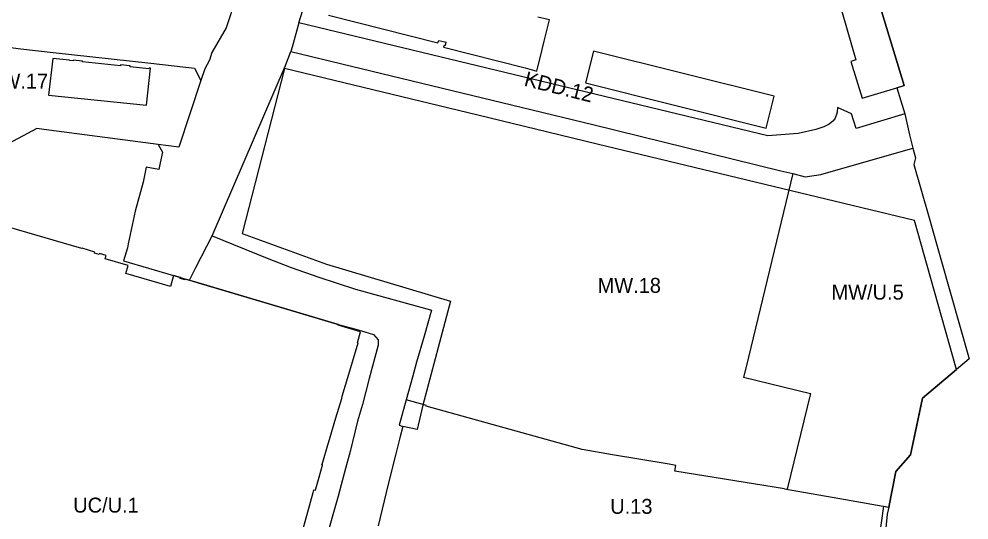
# Model space of a CAD drawing. Extents: x 7424052 to 7425705, y 5546602 to 5547569.
# Drawn here: x 7425164.6 to 7425482.3, y 5546917.7 to 5547085.1 of the extents above; entities that cross this region are included whole.
import ezdxf

# ---------------------------------------------------------------- set-up
doc = ezdxf.new("R2010")
doc.units = 0
for name, color, linetype in [('linie rozgraniczające', 7, 'Continuous'), ('nieprzekraczalne linie zabudowy', 7, 'Continuous'), ('obowiazujace linie zabudowy', 7, 'Continuous'), ('przeznaczenia terenów', 7, 'Continuous')]:
    doc.layers.add(name, color=color, linetype=linetype)

msp = doc.modelspace()

# ---------------------------------------------------------------- linework, layer by layer
at = {"layer": 'linie rozgraniczające'}
for p, q in [((7425258.21, 5547083.79), (7425262.57, 5547097.9)), ((7425237.13, 5547092.01), (7425233.89, 5547082.13)), ((7425233.89, 5547082.13), (7425229.11, 5547073.88)), ((7425258.21, 5547083.79), (7425255.98, 5547075.66)), ((7425305.74, 5547072.33), (7425258.21, 5547083.79)), ((7425160.05, 5547075.79), (7425165.13, 5547075.14)), ((7425165.13, 5547075.14), (7425176.01, 5547073.94)), ((7425255.98, 5547075.66), (7425255.44, 5547074.17)), ((7425176.01, 5547073.94), (7425208.62, 5547070.34)), ((7425228.29, 5547071.34), (7425226.68, 5547068.43)), ((7425229.11, 5547073.88), (7425228.29, 5547071.34)), ((7425253.74, 5547069.49), (7425255.44, 5547074.17)), ((7425255.44, 5547074.17), (7425356.5, 5547049.81)), ((7425415.01, 5547045.99), (7425305.74, 5547072.33)), ((7425208.62, 5547070.34), (7425223.21, 5547068.63)), ((7425223.21, 5547068.63), (7425225.42, 5547064.54)), ((7425226.68, 5547068.43), (7425225.42, 5547064.54)), ((7425229.17, 5547012.59), (7425253.74, 5547069.49)), ((7425225.42, 5547064.54), (7425218.05, 5547042.21)), ((7425438.33, 5547055.56), (7425438.25, 5547053.97)), ((7425442.95, 5547053.38), (7425438.33, 5547055.56)), ((7425438.01, 5547053.15), (7425437.4, 5547051.75)), ((7425438.25, 5547053.97), (7425438.01, 5547053.15)), ((7425444.55, 5547048.46), (7425442.95, 5547053.38)), ((7425460.79, 5547053.42), (7425444.55, 5547048.46)), ((7425460.79, 5547053.42), (7425462.35, 5547046.32)), ((7425356.5, 5547049.81), (7425419.41, 5547034.39)), ((7425433.8, 5547049.07), (7425431.08, 5547048.19)), ((7425435.55, 5547049.93), (7425433.8, 5547049.07)), ((7425436.8, 5547050.91), (7425435.55, 5547049.93)), ((7425437.4, 5547051.75), (7425436.8, 5547050.91)), ((7425170.57, 5547048.5), (7425159.48, 5547042.54)), ((7425172.88, 5547048.19), (7425170.57, 5547048.5)), ((7425211.16, 5547043.12), (7425172.88, 5547048.19)), ((7425425.13, 5547046.83), (7425415.01, 5547045.99)), ((7425431.08, 5547048.19), (7425425.13, 5547046.83)), ((7425211.16, 5547043.12), (7425212.55, 5547040.53)), ((7425218.05, 5547042.21), (7425211.16, 5547043.12)), ((7425212.55, 5547040.53), (7425211.81, 5547036.98)), ((7425432.7, 5547033.14), (7425463.51, 5547041.87)), ((7425463.51, 5547041.87), (7425464.41, 5547038.69)), ((7425211.81, 5547036.98), (7425211.35, 5547034.78)), ((7425464.41, 5547038.69), (7425463.86, 5547036.5)), ((7425207.08, 5547035.52), (7425206.12, 5547030.53)), ((7425211.35, 5547034.78), (7425207.08, 5547035.52)), ((7425423.34, 5547033.41), (7425407.72, 5546968.9)), ((7425419.41, 5547034.39), (7425423.34, 5547033.41)), ((7425423.34, 5547033.41), (7425427.55, 5547032.35)), ((7425427.55, 5547032.35), (7425432.7, 5547033.14)), ((7425206.12, 5547030.53), (7425203.47, 5547020.9)), ((7425203.47, 5547020.9), (7425201.1, 5547010)), ((7425223.75, 5547002.02), (7425229.17, 5547012.59)), ((7425229.17, 5547012.59), (7425247.59, 5547005.15)), ((7425200.82, 5547008.57), (7425199.5, 5547004.32)), ((7425201.1, 5547010), (7425200.82, 5547008.57)), ((7425247.59, 5547005.15), (7425255.54, 5547002.04)), ((7425199.5, 5547004.32), (7425216.28, 5546999.34)), ((7425221.58, 5546997.79), (7425223.75, 5547002.02)), ((7425255.54, 5547002.04), (7425264.86, 5546998.81)), ((7425216.28, 5546999.34), (7425216.28, 5546999.34)), ((7425216.28, 5546999.34), (7425218.6, 5546998.67)), ((7425218.6, 5546998.67), (7425220.21, 5546998.19)), ((7425220.21, 5546998.19), (7425221.58, 5546997.79)), ((7425264.86, 5546998.81), (7425277.12, 5546994.82)), ((7425221.58, 5546997.79), (7425224.49, 5546996.88)), ((7425224.49, 5546996.88), (7425247.74, 5546990)), ((7425277.12, 5546994.82), (7425302.21, 5546987.85)), ((7425247.74, 5546990), (7425270.99, 5546983.13)), ((7425302.56, 5546987.75), (7425300.08, 5546979.12)), ((7425302.21, 5546987.85), (7425302.56, 5546987.75)), ((7425270.99, 5546983.13), (7425271.32, 5546983.01)), ((7425271.32, 5546983.01), (7425277.24, 5546981.48)), ((7425277.24, 5546981.48), (7425280.21, 5546980.49)), ((7425280.21, 5546980.49), (7425283.12, 5546979.63)), ((7425283.12, 5546979.63), (7425284.73, 5546977.89)), ((7425300.08, 5546979.12), (7425297.55, 5546970.38)), ((7425284.65, 5546976.04), (7425281.71, 5546964.96)), ((7425284.73, 5546977.89), (7425284.65, 5546976.04)), ((7425297.55, 5546970.38), (7425296.17, 5546965.43)), ((7425407.72, 5546968.9), (7425406.88, 5546965.41)), ((7425281.71, 5546964.96), (7425279.42, 5546956.23)), ((7425296.17, 5546965.43), (7425294.07, 5546957.83)), ((7425406.88, 5546965.41), (7425429.3, 5546959.97)), ((7425429.3, 5546959.97), (7425421.53, 5546927.92)), ((7425294.07, 5546957.83), (7425291.69, 5546949.4)), ((7425300.82, 5546955.97), (7425294.07, 5546957.83)), ((7425279.42, 5546956.23), (7425277.8, 5546950.71)), ((7425300.77, 5546955.76), (7425300.82, 5546955.97)), ((7425346.85, 5546942.88), (7425300.77, 5546955.76)), ((7425277.8, 5546950.71), (7425275.28, 5546940.53)), ((7425291.69, 5546949.4), (7425292.9, 5546948.93)), ((7425292.9, 5546948.93), (7425291.92, 5546945.18)), ((7425291.92, 5546945.18), (7425290.57, 5546939.81)), ((7425352.87, 5546941.21), (7425346.85, 5546942.88)), ((7425363.04, 5546939.46), (7425352.87, 5546941.21)), ((7425275.28, 5546940.53), (7425273.75, 5546934.91)), ((7425290.57, 5546939.81), (7425288.06, 5546929.59)), ((7425371.82, 5546937.95), (7425363.04, 5546939.46)), ((7425381.99, 5546936.27), (7425371.82, 5546937.95)), ((7425462.73, 5546939.43), (7425457.87, 5546933.9)), ((7425273.75, 5546934.91), (7425271.28, 5546925.67)), ((7425384.28, 5546935.88), (7425381.99, 5546936.27)), ((7425383.93, 5546934.01), (7425384.28, 5546935.88)), ((7425420.55, 5546928.09), (7425383.93, 5546934.01)), ((7425457.87, 5546933.9), (7425455.47, 5546921.95)), ((7425288.06, 5546929.59), (7425284.64, 5546915.69)), ((7425271.28, 5546925.67), (7425264.86, 5546903.09)), ((7425420.55, 5546928.09), (7425440.98, 5546924.47)), ((7425440.98, 5546924.47), (7425455.47, 5546921.95)), ((7425455.47, 5546921.95), (7425454.97, 5546919.66)), ((7425454.97, 5546919.66), (7425454, 5546910.51))]:
    msp.add_line(p, q, dxfattribs=at)
for points in [[(7425444.26, 5547116.94), (7425452.42, 5547089.88), (7425460.58, 5547062.82)], [(7425460.58, 5547062.82), (7425459.36, 5547062.45), (7425458.15, 5547062.09)], [(7425458.15, 5547062.09), (7425459.47, 5547057.75), (7425460.79, 5547053.42)], [(7425462.35, 5547046.32), (7425462.93, 5547044.09), (7425463.51, 5547041.87)], [(7425463.86, 5547036.5), (7425468.71, 5547019.43), (7425473.08, 5547004.04), (7425482.3, 5546971.57), (7425482.3, 5546971.57)], [(7425482.3, 5546971.57), (7425474.54, 5546964.95), (7425466.78, 5546958.33)], [(7425466.78, 5546958.33), (7425464.85, 5546949.31), (7425462.73, 5546939.43)]]:
    msp.add_lwpolyline(points, dxfattribs=at)
at = {"layer": 'nieprzekraczalne linie zabudowy'}
for p, q in [((7425253.31, 5547068.54), (7425239.25, 5547013.36)), ((7425468.27, 5547002.67), (7425464.07, 5547017.79)), ((7425239.25, 5547013.36), (7425267.37, 5547003.21)), ((7425267.37, 5547003.21), (7425308.87, 5546990.81)), ((7425478.12, 5546968), (7425468.27, 5547002.67)), ((7425308.87, 5546990.81), (7425299.66, 5546956)), ((7425466.78, 5546958.33), (7425478.12, 5546968)), ((7425462.73, 5546939.43), (7425466.78, 5546958.33)), ((7425299.66, 5546956), (7425297.72, 5546947.88)), ((7425292.9, 5546948.93), (7425291.92, 5546945.18)), ((7425297.72, 5546947.88), (7425292.9, 5546948.93)), ((7425291.92, 5546945.18), (7425290.57, 5546939.81)), ((7425290.57, 5546939.81), (7425288.06, 5546929.59)), ((7425457.87, 5546933.9), (7425462.73, 5546939.43)), ((7425455.47, 5546921.95), (7425457.87, 5546933.9)), ((7425288.06, 5546929.59), (7425284.64, 5546915.69)), ((7425452.26, 5546911.19), (7425453.8, 5546922.24)), ((7425453.8, 5546922.24), (7425455.47, 5546921.95))]:
    msp.add_line(p, q, dxfattribs=at)
at = {"layer": 'obowiazujace linie zabudowy'}
for p, q in [((7425435.97, 5547100.84), (7425444.5, 5547071.39)), ((7425460.58, 5547062.82), (7425452.42, 5547089.88)), ((7425444.5, 5547071.39), (7425442.82, 5547070.87)), ((7425442.82, 5547070.87), (7425446.53, 5547058.59)), ((7425446.53, 5547058.59), (7425458.15, 5547062.09)), ((7425458.15, 5547062.09), (7425460.58, 5547062.82))]:
    msp.add_line(p, q, dxfattribs=at)
for points in [[(7425268.05, 5547086.33), (7425304.7, 5547077.14), (7425304.93, 5547077.95), (7425307.02, 5547077.45), (7425307.37, 5547077.37), (7425307.09, 5547076.17), (7425306.73, 5547076.27), (7425306.58, 5547075.67), (7425333.86, 5547068.73), (7425333.86, 5547068.73), (7425337.72, 5547067.68), (7425337.83, 5547068.11), (7425339.53, 5547074.91), (7425340.19, 5547077.62), (7425341.94, 5547084.39), (7425342.05, 5547084.81), (7425338.1, 5547085.73)], [(7425356.76, 5547074.38), (7425354.06, 5547063.7), (7425414.45, 5547048.56), (7425417.15, 5547059.24), (7425356.76, 5547074.38)], [(7425175.84, 5547071.9), (7425174.39, 5547059.6), (7425207.25, 5547056.26), (7425208.57, 5547068.63), (7425208.08, 5547068.66), (7425208.04, 5547068.47), (7425201.72, 5547069.12), (7425201.74, 5547069.42), (7425198.53, 5547069.74), (7425198.46, 5547069.46), (7425185.81, 5547070.75), (7425185.82, 5547071.02), (7425182.63, 5547071.34), (7425182.63, 5547071.05), (7425181.49, 5547071.19), (7425181.49, 5547071.34), (7425175.84, 5547071.9)], [(7425464.07, 5547017.79), (7425357.92, 5547043.25), (7425341.48, 5547047.23), (7425318.02, 5547052.94), (7425279.67, 5547062.22), (7425253.31, 5547068.54)], [(7425257.02, 5546905.42), (7425262.9, 5546926.87), (7425263.15, 5546927.75), (7425263.6, 5546927.65), (7425263.62, 5546927.73), (7425263.71, 5546927.7), (7425263.82, 5546928.06), (7425264.93, 5546931.93), (7425266.13, 5546935.94), (7425266.16, 5546936.03), (7425265.89, 5546936.1), (7425265.96, 5546936.31), (7425266.15, 5546936.99), (7425267.91, 5546942.78), (7425268.1, 5546943.47), (7425270.56, 5546951.82), (7425272.5, 5546958.31), (7425272.69, 5546959.04), (7425274.86, 5546966.36), (7425277.96, 5546976.87), (7425277.73, 5546976.92), (7425278.79, 5546980.57), (7425273.49, 5546982.15), (7425271.27, 5546982.78), (7425271.32, 5546983.01), (7425270.99, 5546983.13), (7425224.49, 5546996.88), (7425224.51, 5546996.93), (7425220.21, 5546998.19), (7425220.11, 5546997.88), (7425218.5, 5546998.35), (7425218.6, 5546998.67), (7425216.28, 5546999.34), (7425215.22, 5546995.65), (7425200.35, 5547000.05), (7425201.1, 5547002.67), (7425193.44, 5547004.98), (7425193.74, 5547006.03), (7425191.48, 5547006.72), (7425191.39, 5547006.41), (7425189.79, 5547006.87), (7425189.88, 5547007.19), (7425185.64, 5547008.45), (7425185.61, 5547008.34), (7425185.56, 5547008.35), (7425139.05, 5547021.86)]]:
    msp.add_lwpolyline(points, dxfattribs=at)

# ---------------------------------------------------------------- texts
at = {"layer": 'przeznaczenia terenów'}
for s, p in [('MW.17', (7425153.14, 5547061.83)), ('MW.18', (7425358.09, 5546993.57)), ('MW/U.5', (7425436.32, 5546991.31)), ('UC/U.1', (7425182.7, 5546920.14)), ('U.13', (7425362.31, 5546919.73))]:
    msp.add_text(s, height=5, dxfattribs=at).set_placement(p)
msp.add_text('KDD.12', height=5, rotation=346, dxfattribs=at).set_placement((7425333.22, 5547062.81))

doc.saveas('drawing.dxf')
